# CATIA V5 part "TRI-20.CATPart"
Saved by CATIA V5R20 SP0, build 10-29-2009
Part number: _TRI-20
Definition: NONE
Nomenclature: _TRI-20
Source: Unknown
Description: PART-_TRI-20-DESC
Bounding box of the stored display mesh (mm): x 0 to 22.5, y -10 to 10, z -10 to 10
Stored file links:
  C:\Users\Utente\Desktop\IO LAVORO\3D X SITO CF\X SITO\PLASTICA\TRI\TRI-20.CATPart
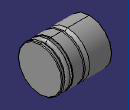
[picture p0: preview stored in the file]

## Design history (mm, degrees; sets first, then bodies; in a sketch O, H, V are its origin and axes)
Body1 "_TRI-20" (main body)
  Solid1: solid without history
